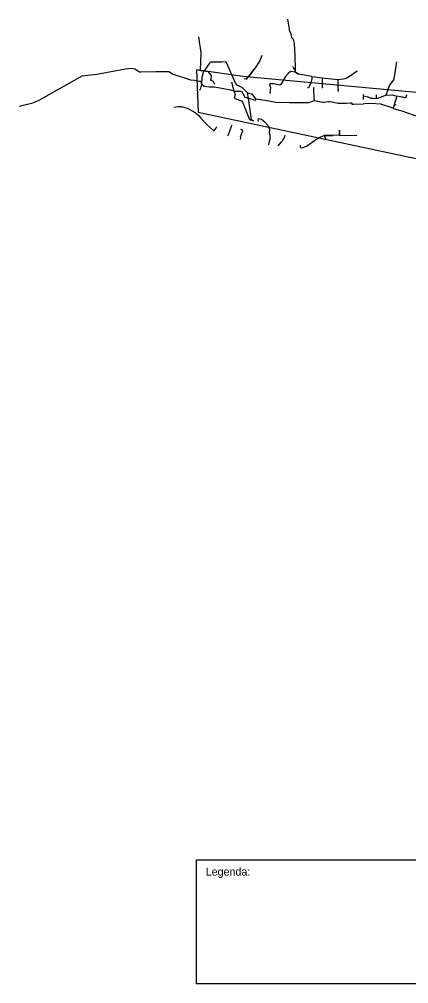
# Model space of a CAD drawing. Extents: x -521722 to -519596, y -1060201 to -1058393.
# Drawn here: x -521722 to -520992, y -1060201 to -1058393 of the extents above; entities that cross this region are included whole.
import ezdxf

# ---------------------------------------------------------------- set-up
doc = ezdxf.new("R2010")
doc.units = 0
for name, color, linetype in [('Vrstva 1', 7, 'Continuous'), ('Vrstva 2', 7, 'Continuous'), ('Vrstva 63', 7, 'Continuous')]:
    doc.layers.add(name, color=color, linetype=linetype)

msp = doc.modelspace()

# ---------------------------------------------------------------- linework, layer by layer
at = {"layer": 'Vrstva 1'}
for points in [[(-521204.04, -1058488.52), (-521204.97, -1058461.01), (-521205.99, -1058438.76), (-521207.78, -1058431.42), (-521209.29, -1058430.31), (-521211.01, -1058428.12), (-521211.86, -1058422.35), (-521212.38, -1058420.99), (-521214.72, -1058416.22), (-521215.16, -1058413.74), (-521215.45, -1058411.87), (-521218.56, -1058393.43)], [(-521382.49, -1058489.11), (-521381.38, -1058456.51), (-521385.59, -1058426.19)], [(-521267.37, -1058461.11), (-521271.04, -1058470.59), (-521279.01, -1058483.56), (-521282.05, -1058487.66), (-521287.81, -1058495.5), (-521296.82, -1058505.34), (-521300.62, -1058504.82)], [(-521034.02, -1058535.81), (-521032.76, -1058532.16), (-521027.57, -1058517.21), (-521019.73, -1058506.65), (-521019.02, -1058504.71), (-521016.5, -1058489.6), (-521014.25, -1058473.39)], [(-521382.49, -1058489.11), (-521385.01, -1058489.11), (-521385.19, -1058489.11)], [(-521382.49, -1058489.11), (-521385.01, -1058489.11)], [(-521382.49, -1058489.11), (-521368.4, -1058491.36), (-521362.43, -1058498.78), (-521362.8, -1058507.54)], [(-521296.82, -1058505.34), (-521287.81, -1058495.5), (-521282.05, -1058487.66)], [(-521204.19, -1058492.57), (-521213.44, -1058491.36), (-521217.58, -1058495.03), (-521222.65, -1058500.44), (-521231.67, -1058515.45), (-521233.61, -1058516.7), (-521245.53, -1058514.53), (-521251.7, -1058514.14), (-521252.67, -1058515.68), (-521251.08, -1058521.04), (-521252.46, -1058531.49), (-521251.19, -1058531.88)], [(-521204.04, -1058488.52), (-521207.77, -1058484.23), (-521209.16, -1058482.08)], [(-521204.19, -1058492.57), (-521204.04, -1058488.52)], [(-521204.19, -1058492.57), (-521198.2, -1058496.31)], [(-521173.69, -1058500.77), (-521180.52, -1058499.68), (-521198.2, -1058496.31), (-521204.19, -1058492.57)], [(-521124.67, -1058506.35), (-521113.93, -1058505.28), (-521109.34, -1058503.69), (-521103.05, -1058500.04), (-521088.32, -1058489.89)], [(-521362.8, -1058507.54), (-521363.99, -1058507.39)], [(-521362.8, -1058507.54), (-521358.84, -1058509.7), (-521356.51, -1058513.59), (-521355.26, -1058513.59)], [(-521173.69, -1058500.77), (-521173.58, -1058501.41), (-521173.48, -1058504.99), (-521174.46, -1058509.94), (-521176.04, -1058513.66), (-521177.67, -1058517.39), (-521178.59, -1058519.62)], [(-521177.67, -1058517.39), (-521176.04, -1058513.66)], [(-521173.69, -1058500.77), (-521154.09, -1058503.34)], [(-521154.09, -1058503.34), (-521154.08, -1058512.95), (-521153.79, -1058520.32), (-521153.73, -1058522.06), (-521154.9, -1058522.19)], [(-521154.09, -1058503.34), (-521124.67, -1058506.35)], [(-521154.08, -1058512.95), (-521153.79, -1058520.32)], [(-521124.67, -1058506.35), (-521124.57, -1058515.17), (-521124.43, -1058521.02), (-521124.29, -1058527.94), (-521125.02, -1058528.4)], [(-521124.57, -1058515.17), (-521124.43, -1058521.02)], [(-521178.59, -1058519.62), (-521179.65, -1058521.6), (-521181.34, -1058521.88)], [(-521076.34, -1058536.76), (-521076.94, -1058540.03), (-521076.89, -1058542.87), (-521077.55, -1058542.99), (-521077.62, -1058543)], [(-521076.34, -1058536.76), (-521076.71, -1058534.66)], [(-521076.34, -1058536.76), (-521071.04, -1058538.37), (-521068.65, -1058538.67), (-521062.46, -1058541.28), (-521058.54, -1058541.32), (-521052.07, -1058541.74)], [(-521068.65, -1058538.67), (-521062.46, -1058541.28)], [(-521052.07, -1058541.74), (-521052.37, -1058535.22)], [(-521052.07, -1058541.74), (-521045.56, -1058540.23), (-521042.63, -1058538.99), (-521038.2, -1058537.11), (-521034.02, -1058535.81)], [(-521042.63, -1058538.99), (-521038.2, -1058537.11)], [(-521034.02, -1058535.81), (-521022.5, -1058535.15), (-521013.97, -1058537.2)], [(-521013.97, -1058537.2), (-521019.84, -1058555.8), (-521018.77, -1058556.32)], [(-520994.82, -1058536.19), (-520996.15, -1058536.3), (-520996.97, -1058540.53), (-520997.44, -1058540.86), (-521003.25, -1058539.18), (-521004.5, -1058539.17), (-521007.25, -1058538.91), (-521013.97, -1058537.2)], [(-521432.47, -1058557.91), (-521424.42, -1058556.73), (-521417.95, -1058557.1), (-521407.18, -1058559.92)], [(-521432.47, -1058557.91), (-521424.42, -1058556.73), (-521417.95, -1058557.1), (-521407.18, -1058559.92), (-521395.5, -1058566.33), (-521391.58, -1058569.03), (-521385.77, -1058573.94), (-521382.32, -1058578.08), (-521369.38, -1058591.57), (-521357.97, -1058601.63), (-521356.75, -1058602.7)], [(-521254.43, -1058628.64), (-521252.73, -1058621.54), (-521251.09, -1058614.74), (-521252.93, -1058605.74), (-521252.03, -1058599.91), (-521254.4, -1058594.21), (-521261.36, -1058586.15), (-521267.8, -1058581.05), (-521274.19, -1058579.87), (-521274.94, -1058582.32), (-521274.4, -1058584.8)], [(-521356.75, -1058602.7), (-521353.84, -1058597.95), (-521351.7, -1058594.44)], [(-521356.75, -1058602.7), (-521353.84, -1058597.95)], [(-521330.94, -1058612.07), (-521329.37, -1058608.14), (-521323.69, -1058591.79), (-521322.95, -1058592.08)], [(-521307.35, -1058619.01), (-521306.83, -1058614.65), (-521307.1, -1058613.71), (-521303.09, -1058602.31), (-521304.28, -1058600.7), (-521307.02, -1058599.67)], [(-521252.93, -1058605.74), (-521252.03, -1058599.91)], [(-521121.26, -1058601.1), (-521121.26, -1058601.21), (-521121.38, -1058610.37)], [(-521121.38, -1058610.37), (-521121.26, -1058601.21)], [(-521236.54, -1058630.71), (-521231.18, -1058624), (-521228.6, -1058620.94), (-521227.73, -1058619.91), (-521224.91, -1058614.99), (-521223.48, -1058610.75), (-521223.44, -1058610.64)], [(-521231.18, -1058624), (-521228.6, -1058620.94)], [(-521195.04, -1058633.96), (-521192.24, -1058634.05), (-521183.28, -1058631.11), (-521162.05, -1058616.16), (-521157.45, -1058613.75), (-521150.04, -1058611.38)], [(-521162.05, -1058616.16), (-521157.45, -1058613.75)], [(-521121.38, -1058610.37), (-521133.72, -1058610.94), (-521136.26, -1058611.07), (-521148.12, -1058610.92), (-521150.04, -1058611.38)], [(-521150.04, -1058611.38), (-521148.12, -1058610.92), (-521136.26, -1058611.07), (-521133.72, -1058610.94)], [(-521150.04, -1058611.38), (-521147.6, -1058617.58), (-521148.12, -1058618.57), (-521149.79, -1058619.32)], [(-521121.38, -1058610.37), (-521093.69, -1058611.38), (-521089.26, -1058610.86)], [(-521195.04, -1058633.96), (-521194.8, -1058629.07)], [(-521195.04, -1058633.96), (-521194.8, -1058629.07)]]:
    msp.add_lwpolyline(points, dxfattribs=at)
msp.add_lwpolyline([(-521389.75, -1059968.72), (-520169.73, -1059968.72), (-520169.73, -1060200.79), (-521389.75, -1060200.79)], close=True, dxfattribs=at)
at = {"layer": 'Vrstva 2'}
for points in [[(-521376.5, -1058492.37), (-521364.77, -1058475.69)], [(-521364.77, -1058475.69), (-521363.44, -1058473.45), (-521362.04, -1058473.42), (-521360.01, -1058473.36), (-521342.19, -1058472.98), (-521334.71, -1058472.79), (-521316.62, -1058513.51), (-521315.12, -1058516.36), (-521305.12, -1058520.34), (-521293.93, -1058531.44)], [(-521380.15, -1058515.1), (-521381.52, -1058510.07), (-521384.33, -1058509.81), (-521393.75, -1058508.32), (-521400.57, -1058507.45), (-521435.01, -1058496.05), (-521442.08, -1058492.02), (-521443.19, -1058492.03), (-521466.17, -1058491.8), (-521495.18, -1058492.44), (-521496.55, -1058492.49), (-521505.44, -1058486.6), (-521511.88, -1058485.75), (-521523.36, -1058486.62), (-521577.03, -1058497.09), (-521604.84, -1058499.98), (-521686.96, -1058545.96), (-521699.69, -1058551.03), (-521722.48, -1058556.73)], [(-521380.15, -1058515.1), (-521379.23, -1058502.13), (-521379.26, -1058501.6), (-521376.5, -1058492.37)], [(-521380.15, -1058515.1), (-521380.87, -1058517.51), (-521383.13, -1058524.74), (-521383.43, -1058525.61), (-521384.4, -1058525.39)], [(-521380.15, -1058515.1), (-521375.79, -1058518.84), (-521365.54, -1058519.84), (-521355.83, -1058520.25), (-521339.39, -1058523.25), (-521325.92, -1058525.79), (-521319.53, -1058527.33), (-521317.28, -1058527.87), (-521305.39, -1058528.34), (-521299.42, -1058539.52), (-521292.57, -1058541.32), (-521279.26, -1058544.81), (-521278.34, -1058543.37)], [(-521324.19, -1058510.59), (-521319.53, -1058527.33), (-521317.6, -1058534.24), (-521319.46, -1058541.34), (-521304.44, -1058546.57), (-521290.26, -1058581.54), (-521282.83, -1058583.92), (-521287, -1058581.58), (-521292.57, -1058541.32), (-521293.93, -1058531.44)], [(-521293.93, -1058531.44), (-521289.23, -1058532.49)], [(-521289.23, -1058532.49), (-521286.28, -1058533.18), (-521281.11, -1058540.09), (-521278.34, -1058543.37)], [(-521169.4, -1058522.06), (-521170.53, -1058522.11), (-521169.64, -1058540.62), (-521169.38, -1058546.43)], [(-521169.38, -1058546.43), (-521179.93, -1058549.95), (-521194.7, -1058550.08), (-521204.46, -1058549.91), (-521215.36, -1058549.74), (-521241.04, -1058549.26), (-521260.77, -1058545.64), (-521278.34, -1058543.37)], [(-521074.47, -1058552.08), (-521076.97, -1058552.4), (-521095.12, -1058553.11), (-521097.86, -1058553.23), (-521098.07, -1058550.75), (-521101.2, -1058550.8), (-521108.74, -1058551.17), (-521124.31, -1058550.96), (-521139.14, -1058547.95), (-521142.5, -1058548.28), (-521150.7, -1058549.08), (-521153.68, -1058549.38), (-521168.52, -1058546.14), (-521169.38, -1058546.43)], [(-521020.74, -1058560.3), (-521044.19, -1058552.39), (-521053.57, -1058551.89), (-521067.83, -1058551.22), (-521074.47, -1058552.08)], [(-521015.36, -1058554.46), (-521018.42, -1058553.44), (-521020.74, -1058560.3)], [(-521020.74, -1058560.3), (-521020.18, -1058560.56), (-521013.73, -1058562.22)], [(-521013.73, -1058562.22), (-521004.38, -1058565.12), (-520972.92, -1058576.11)]]:
    msp.add_lwpolyline(points, dxfattribs=at)
at = {"layer": 'Vrstva 63'}
msp.add_lwpolyline([(-519891.66, -1059200.79), (-519854.74, -1059097.13), (-520215.42, -1058798.93), (-520455.4, -1058717.99), (-520638.58, -1058561.79), (-521303.13, -1058500.73), (-521389.75, -1058487.95), (-521386.91, -1058567.47), (-520725.2, -1058708.05), (-520469.6, -1058854.31), (-520229.62, -1059013.35), (-520097.56, -1059043.17), (-519891.66, -1059200.79)], close=True, dxfattribs=at)

# ---------------------------------------------------------------- texts
at = {"layer": 'Vrstva 1'}
msp.add_text('Legenda:', height=15, dxfattribs=at).set_placement((-521372.59, -1059998.2))

doc.saveas('drawing.dxf')
